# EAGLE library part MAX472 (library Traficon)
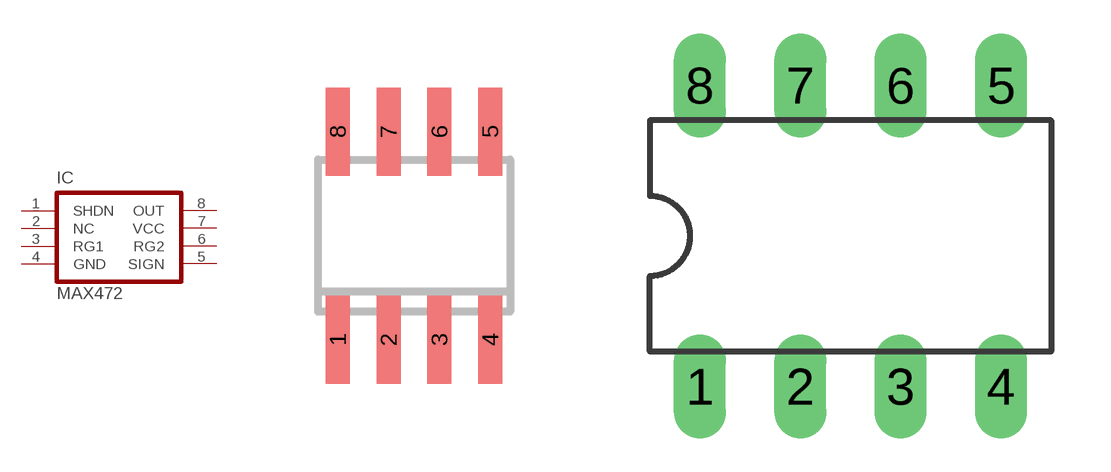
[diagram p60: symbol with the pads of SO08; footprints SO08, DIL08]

Designator prefix IC

## MAX472ESA  [SO08]
1  SHDN
2  NC  nc
3  RG1
4  GND
5  SIGN  out
6  RG2
7  VCC
8  OUT  out

## MAX472CPA  [DIL08]
Pads as for SO08

## Footprint SO08 (pad centres in mm)
Small Outline Package
smd 0.6 x 2.2: 1 -1.905,-2.6; 2 -0.635,-2.6; 3 0.635,-2.6; 4 1.905,-2.6; 5 1.905,2.6; 6 0.635,2.6; 7 -0.635,2.6; 8 -1.905,2.6

## Footprint DIL08 (pad centres in mm)
Dual In Line Package
drill 0.813 long: 1 -3.81,-3.81; 2 -1.27,-3.81; 3 1.27,-3.81; 4 3.81,-3.81; 5 3.81,3.81; 6 1.27,3.81; 7 -1.27,3.81; 8 -3.81,3.81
